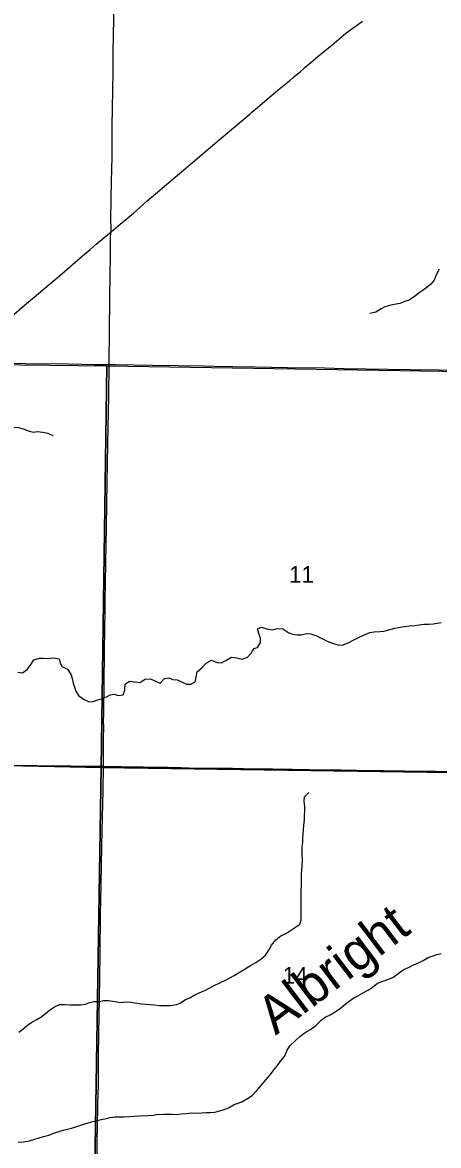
# Model space of a CAD drawing. Extents: x -8.5 to 18.7, y -20.3 to 7.
# Drawn here: x 6.98 to 9.06, y -16.66 to -11.04 of the extents above; entities that cross this region are included whole.
import ezdxf

# ---------------------------------------------------------------- set-up
doc = ezdxf.new("R2010")
doc.units = 0
for name, color, linetype in [('GM_X_County_Road', 7, 'Continuous'), ('GM_X_Minor_River', 7, 'Continuous'), ('GM_X_Minor_River_Text', 7, 'Continuous'), ('GM_X_Section', 7, 'Continuous'), ('GM_X_Section_Text', 7, 'Continuous'), ('GM_X_State_Route', 7, 'Continuous'), ('GM_X_Township_Road', 7, 'Continuous')]:
    doc.layers.add(name, color=color, linetype=linetype)

msp = doc.modelspace()

# ---------------------------------------------------------------- linework, layer by layer
at = {"layer": 'GM_X_County_Road'}
for points in [[(6.6474, -12.7448), (6.6725, -12.7443), (6.741, -12.7448), (6.9101, -12.7471), (6.9884, -12.7484), (7.2047, -12.7508), (7.3352, -12.7531), (7.4089, -12.7537)], [(7.4089, -12.7537), (7.4409, -12.7539), (7.6261, -12.7579), (7.881, -12.761), (7.9345, -12.7618), (8.0277, -12.7639), (8.1408, -12.7654), (8.3012, -12.7687), (8.4852, -12.7714), (8.5834, -12.7731), (8.9141, -12.7783), (9.0583, -12.7805), (9.2286, -12.7829), (9.3629, -12.7848), (9.3952, -12.7854)]]:
    msp.add_lwpolyline(points, dxfattribs=at)
at = {"layer": 'GM_X_Minor_River'}
for points in [[(9.0581, -12.2764), (9.0444, -12.306), (9.0329, -12.3317), (9.0177, -12.3514), (8.9987, -12.3672), (8.9782, -12.3815), (8.9584, -12.3951), (8.9349, -12.4132), (8.9083, -12.4328), (8.8871, -12.4395), (8.862, -12.4485), (8.834, -12.4544), (8.8112, -12.4589), (8.787, -12.4656), (8.768, -12.4761), (8.7414, -12.4927), (8.7126, -12.4987)], [(6.8408, -13.0858), (6.8711, -13.0735), (6.8999, -13.0744), (6.9272, -13.0677), (6.956, -13.0686), (6.9832, -13.0771), (7.0044, -13.0863), (7.0286, -13.0917), (7.0513, -13.0895), (7.0778, -13.0927), (7.1028, -13.0974), (7.127, -13.1096)], [(8.9096, -14.0618), (8.9368, -14.0589), (8.9588, -14.056), (8.9823, -14.0538), (9.0066, -14.0524), (9.0293, -14.051), (9.0482, -14.0473), (9.0687, -14.0451)], [(6.9527, -14.2924), (6.9754, -14.2971), (6.999, -14.2797), (7.018, -14.2533), (7.0318, -14.2313), (7.0606, -14.2224), (7.0803, -14.2225), (7.103, -14.2249), (7.131, -14.2212), (7.159, -14.2259), (7.1635, -14.2456), (7.1725, -14.2646), (7.2013, -14.2784), (7.2193, -14.3066), (7.223, -14.3256), (7.229, -14.3476), (7.235, -14.3689), (7.2417, -14.3879), (7.256, -14.4099), (7.281, -14.429), (7.3082, -14.4413), (7.3287, -14.4391), (7.3514, -14.4309), (7.3704, -14.4264), (7.3954, -14.4159), (7.4144, -14.4069), (7.4341, -14.4032), (7.4538, -14.4093), (7.478, -14.4057), (7.4872, -14.3829), (7.4881, -14.3534), (7.5108, -14.3383), (7.5373, -14.3422), (7.5616, -14.3446), (7.5882, -14.328), (7.6147, -14.3259), (7.6411, -14.3389), (7.6646, -14.3481), (7.6851, -14.3254), (7.7064, -14.3217), (7.7268, -14.3294), (7.748, -14.3318), (7.7956, -14.3525), (7.8168, -14.3526), (7.8396, -14.3413), (7.8435, -14.3178), (7.8496, -14.2921), (7.8732, -14.2702), (7.8937, -14.2475), (7.9211, -14.2332), (7.9483, -14.2455), (7.9703, -14.2456), (7.9923, -14.2351), (8.0204, -14.2177), (8.0476, -14.2217), (8.0741, -14.2279), (8.1007, -14.2189), (8.1189, -14.1985), (8.1319, -14.1743), (8.1509, -14.169), (8.1653, -14.1441), (8.1647, -14.1251), (8.1564, -14.1), (8.1497, -14.0757), (8.1709, -14.0675), (8.1974, -14.0759), (8.2247, -14.0806), (8.2489, -14.0739), (8.2777, -14.0771), (8.3064, -14.0962), (8.3261, -14.1031), (8.3496, -14.107), (8.3693, -14.1063), (8.3966, -14.0989), (8.417, -14.102), (8.445, -14.1112), (8.479, -14.1288), (8.4994, -14.138), (8.5259, -14.1488), (8.5577, -14.1573), (8.5789, -14.1566), (8.6077, -14.1454), (8.632, -14.1311), (8.6616, -14.1168), (8.6882, -14.1055), (8.7125, -14.0943), (8.7344, -14.0921), (8.7617, -14.0899), (8.7822, -14.0878), (8.8072, -14.0818), (8.8368, -14.0728), (8.8557, -14.0691), (8.8861, -14.064), (8.9096, -14.0618)], [(6.9579, -16.0944), (6.9776, -16.0786), (6.9997, -16.059), (7.0224, -16.0446), (7.0467, -16.0303), (7.0672, -16.0191), (7.09, -16.001), (7.1098, -15.9844), (7.1349, -15.967), (7.1599, -15.955), (7.1872, -15.9559), (7.216, -15.9575), (7.2447, -15.9569), (7.2675, -15.9578), (7.2902, -15.9548), (7.3107, -15.9458), (7.3319, -15.9414), (7.3599, -15.94), (7.3804, -15.9355), (7.4054, -15.9349), (7.4259, -15.9388), (7.4478, -15.9427), (7.4683, -15.9451), (7.4925, -15.9421), (7.5175, -15.9445), (7.547, -15.9492), (7.5697, -15.9516), (7.5924, -15.9547), (7.6144, -15.9556), (7.6349, -15.958), (7.6598, -15.9604), (7.6901, -15.9605), (7.7174, -15.9599), (7.7447, -15.9554), (7.7644, -15.9487), (7.7902, -15.9314), (7.8115, -15.9216), (7.8343, -15.9088), (7.8586, -15.8976), (7.8904, -15.8833), (7.9094, -15.8743), (7.9344, -15.8615), (7.9618, -15.8472), (7.9899, -15.8344), (8.0088, -15.8247), (8.0339, -15.8104), (8.0635, -15.7931), (8.0832, -15.7802), (8.1121, -15.7622), (8.1417, -15.7449), (8.1675, -15.729), (8.1896, -15.7087), (8.2071, -15.6845), (8.2208, -15.6595), (8.2429, -15.6323), (8.2672, -15.6119), (8.2892, -15.6014), (8.3097, -15.5893), (8.3355, -15.5728), (8.3629, -15.5532), (8.369, -15.5327), (8.3691, -15.5046), (8.3685, -15.4781), (8.3686, -15.4553), (8.3687, -15.4326), (8.3688, -15.3863), (8.3697, -15.3559), (8.3699, -15.3013), (8.3715, -15.2824), (8.3731, -15.2596), (8.3747, -15.2331), (8.3741, -15.2072), (8.3734, -15.1875), (8.3742, -15.1648), (8.3766, -15.145), (8.3774, -15.1253), (8.3783, -15.1026), (8.3799, -15.0821), (8.3815, -15.0578), (8.3846, -15.0328), (8.3862, -15.0131), (8.3871, -14.9873), (8.3871, -14.9653), (8.3842, -14.9402), (8.3858, -14.916), (8.4079, -14.8956)], [(6.9535, -16.6445), (6.9792, -16.6431), (7.0111, -16.6371), (7.0368, -16.6289), (7.0808, -16.6155), (7.1066, -16.6095), (7.1423, -16.596), (7.1688, -16.5878), (7.1916, -16.5818), (7.2211, -16.5744), (7.2424, -16.5677), (7.2666, -16.5594), (7.2917, -16.5504), (7.3205, -16.5422), (7.3425, -16.5378), (7.369, -16.5303), (7.3948, -16.5259), (7.4145, -16.5214), (7.4372, -16.5185), (7.4585, -16.5178), (7.4819, -16.5172), (7.5122, -16.5158), (7.5357, -16.5136), (7.5607, -16.5122), (7.6032, -16.5109), (7.6282, -16.5088), (7.6479, -16.5066), (7.6812, -16.5052), (7.7047, -16.5046), (7.7259, -16.5047), (7.7501, -16.5063), (7.7691, -16.5033), (7.7971, -16.5012), (7.8206, -16.4983), (7.8433, -16.4991), (7.8706, -16.4977), (7.8918, -16.4963), (7.9146, -16.4957), (7.9365, -16.495), (7.9562, -16.4898), (7.9782, -16.4823), (8.0048, -16.4726), (8.0336, -16.4568), (8.0534, -16.45), (8.0723, -16.4433), (8.0997, -16.426), (8.1232, -16.4117), (8.1468, -16.386), (8.1704, -16.3588), (8.1917, -16.3331), (8.2145, -16.3074), (8.2343, -16.2817), (8.2503, -16.2613), (8.2655, -16.2386), (8.2846, -16.2152), (8.2991, -16.1849), (8.3128, -16.1629), (8.3402, -16.1365), (8.3622, -16.1154), (8.3888, -16.0958), (8.4146, -16.08), (8.4427, -16.0611), (8.4693, -16.0347), (8.4891, -16.0189), (8.5134, -16.0076), (8.5392, -15.9918), (8.565, -15.9744), (8.5886, -15.9533), (8.6083, -15.9397), (8.6319, -15.9232), (8.6524, -15.9119), (8.6759, -15.8998), (8.7017, -15.8833), (8.723, -15.8705), (8.7511, -15.8486), (8.7814, -15.8374), (8.805, -15.8291), (8.827, -15.8209), (8.8536, -15.8013), (8.8786, -15.7824), (8.912, -15.7667), (8.931, -15.7569), (8.9522, -15.7494), (8.9788, -15.7351), (9.0031, -15.7208), (9.0243, -15.7133), (9.0478, -15.7058), (9.0683, -15.7014)]]:
    msp.add_lwpolyline(points, dxfattribs=at)
at = {"layer": 'GM_X_Section'}
for points in [[(5.2797, -12.6788), (6.0987, -12.7461), (7.3966, -12.7605), (7.3681, -14.7705), (6.0431, -14.7415), (5.2437, -14.6964)], [(7.3966, -12.7605), (9.3854, -12.792), (9.3493, -14.7982), (7.3681, -14.7705)], [(5.2437, -14.6964), (6.0431, -14.7415), (7.3681, -14.7705), (7.3365, -16.776), (6.0814, -16.7564), (5.2313, -16.7094)], [(7.3681, -14.7705), (9.3493, -14.7982), (9.3147, -16.8052), (7.3365, -16.776)]]:
    msp.add_lwpolyline(points, close=True, dxfattribs=at)
at = {"layer": 'GM_X_State_Route'}
msp.add_lwpolyline([(6.8235, -12.5954), (6.9957, -12.4487), (7.0558, -12.3985), (7.1725, -12.2995), (7.2763, -12.2105), (7.3142, -12.1783), (7.3443, -12.1523), (7.41, -12.0971), (7.4182, -12.0902), (7.4546, -12.0595), (7.5297, -11.9961), (7.5973, -11.9375), (7.7172, -11.8348), (7.7817, -11.7801), (7.9592, -11.6299), (8.0508, -11.5534), (8.1136, -11.5006), (8.1229, -11.4923), (8.1498, -11.4683), (8.1641, -11.4564), (8.2084, -11.4183), (8.2405, -11.3908), (8.2635, -11.3719), (8.2775, -11.3616), (8.2871, -11.3537), (8.312, -11.3331), (8.3272, -11.3203), (8.3412, -11.3081), (8.3537, -11.2978), (8.365, -11.2881), (8.381, -11.2742), (8.3895, -11.2669), (8.4178, -11.2427), (8.4622, -11.2047), (8.5215, -11.1556), (8.5579, -11.1255), (8.5807, -11.1064), (8.5924, -11.0971), (8.6391, -11.0622), (8.65, -11.0539), (8.6752, -11.0358)], dxfattribs=at)
at = {"layer": 'GM_X_Township_Road'}
for points in [[(7.4237, -11.6555), (7.4244, -11.5579), (7.4257, -11.4758), (7.4268, -11.3788), (7.4284, -11.2917), (7.4292, -11.191), (7.4305, -11.1077), (7.4314, -11.0231), (7.4333, -10.8975), (7.4352, -10.8154), (7.4354, -10.804)], [(7.4182, -12.0902), (7.4188, -12.0834), (7.419, -12.0769), (7.4186, -12.069), (7.4174, -12.0342), (7.4196, -11.9222), (7.4209, -11.8393), (7.4232, -11.7133), (7.4237, -11.6555)], [(7.4089, -12.7537), (7.4092, -12.7338), (7.4102, -12.5971), (7.4116, -12.4193), (7.4132, -12.3124), (7.4149, -12.2017), (7.4147, -12.1619), (7.4158, -12.1127), (7.4163, -12.1056), (7.4167, -12.0996), (7.4182, -12.0902)], [(7.3879, -14.0533), (7.3882, -14.0056), (7.3894, -13.9385), (7.3903, -13.844), (7.3914, -13.7483), (7.3947, -13.5655), (7.3984, -13.343), (7.4022, -13.1528), (7.4041, -13.0695), (7.4068, -12.9104), (7.4089, -12.7537)], [(7.3798, -14.7641), (7.3799, -14.755), (7.3801, -14.7239), (7.3805, -14.6705), (7.3809, -14.6233), (7.3815, -14.5698), (7.3811, -14.5374), (7.3814, -14.5064), (7.3825, -14.4344), (7.383, -14.4009), (7.3838, -14.33), (7.3857, -14.2083), (7.3878, -14.0553), (7.3879, -14.0533)], [(6.969, -14.7594), (6.9801, -14.7599), (6.9862, -14.7598), (6.9997, -14.76), (7.0096, -14.7598), (7.0194, -14.7602), (7.0404, -14.7607), (7.0479, -14.7606), (7.0677, -14.7609), (7.085, -14.7611), (7.096, -14.7606), (7.1071, -14.761), (7.1145, -14.7611), (7.1666, -14.762), (7.2149, -14.7621), (7.2994, -14.7633), (7.3541, -14.7636), (7.3714, -14.764), (7.3798, -14.7641)], [(7.3552, -16.2911), (7.3561, -16.2021), (7.3578, -16.1101), (7.3592, -16.0044), (7.3599, -15.9361), (7.3619, -15.8154), (7.3634, -15.6998), (7.3662, -15.5059), (7.3684, -15.3579), (7.3707, -15.2535), (7.3745, -15.0845), (7.3782, -14.8868), (7.3798, -14.7641)], [(7.3798, -14.7641), (7.3988, -14.7645), (7.4199, -14.7649), (7.4684, -14.7656), (7.5081, -14.7661), (7.5683, -14.7665), (7.5791, -14.767), (7.6025, -14.7677), (7.6161, -14.7681), (7.6283, -14.7683), (7.6395, -14.7687), (7.6554, -14.7685), (7.6814, -14.7687), (7.7049, -14.769), (7.7273, -14.7693), (7.7347, -14.7694), (7.7682, -14.7701), (7.8068, -14.771), (7.9497, -14.7728), (8.0256, -14.7741), (8.1374, -14.7759), (8.2133, -14.7771), (8.2269, -14.777), (8.3251, -14.7789), (8.4942, -14.7809), (8.5688, -14.7824), (8.6459, -14.7834), (8.7826, -14.7853), (8.8846, -14.7867), (9.04, -14.7889), (9.2004, -14.791)], [(7.3471, -16.771), (7.3482, -16.6955), (7.3491, -16.6421), (7.3504, -16.5612), (7.3523, -16.468), (7.3541, -16.3922), (7.355, -16.3649), (7.3548, -16.3376), (7.3552, -16.2911)]]:
    msp.add_lwpolyline(points, dxfattribs=at)

# ---------------------------------------------------------------- texts
at = {"layer": 'GM_X_Minor_River_Text'}
msp.add_text('Albright', height=0.18949, rotation=37.2145, dxfattribs=at).set_placement((8.2412, -16.1122))
at = {"layer": 'GM_X_Section_Text'}
for s, p in [('11', (8.3082, -13.8459)), ('14', (8.2765, -15.852))]:
    msp.add_text(s, height=0.08371, rotation=0, dxfattribs=at).set_placement(p)

doc.saveas('drawing.dxf')
